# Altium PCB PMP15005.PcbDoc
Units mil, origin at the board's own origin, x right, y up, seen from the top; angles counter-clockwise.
Board outline 2000 x 1700 mil, 2 copper layers (Top Layer, Bottom Layer), stack 61.6 mil thick; 50 components, 16 nets, 81 pads, 20 vias.
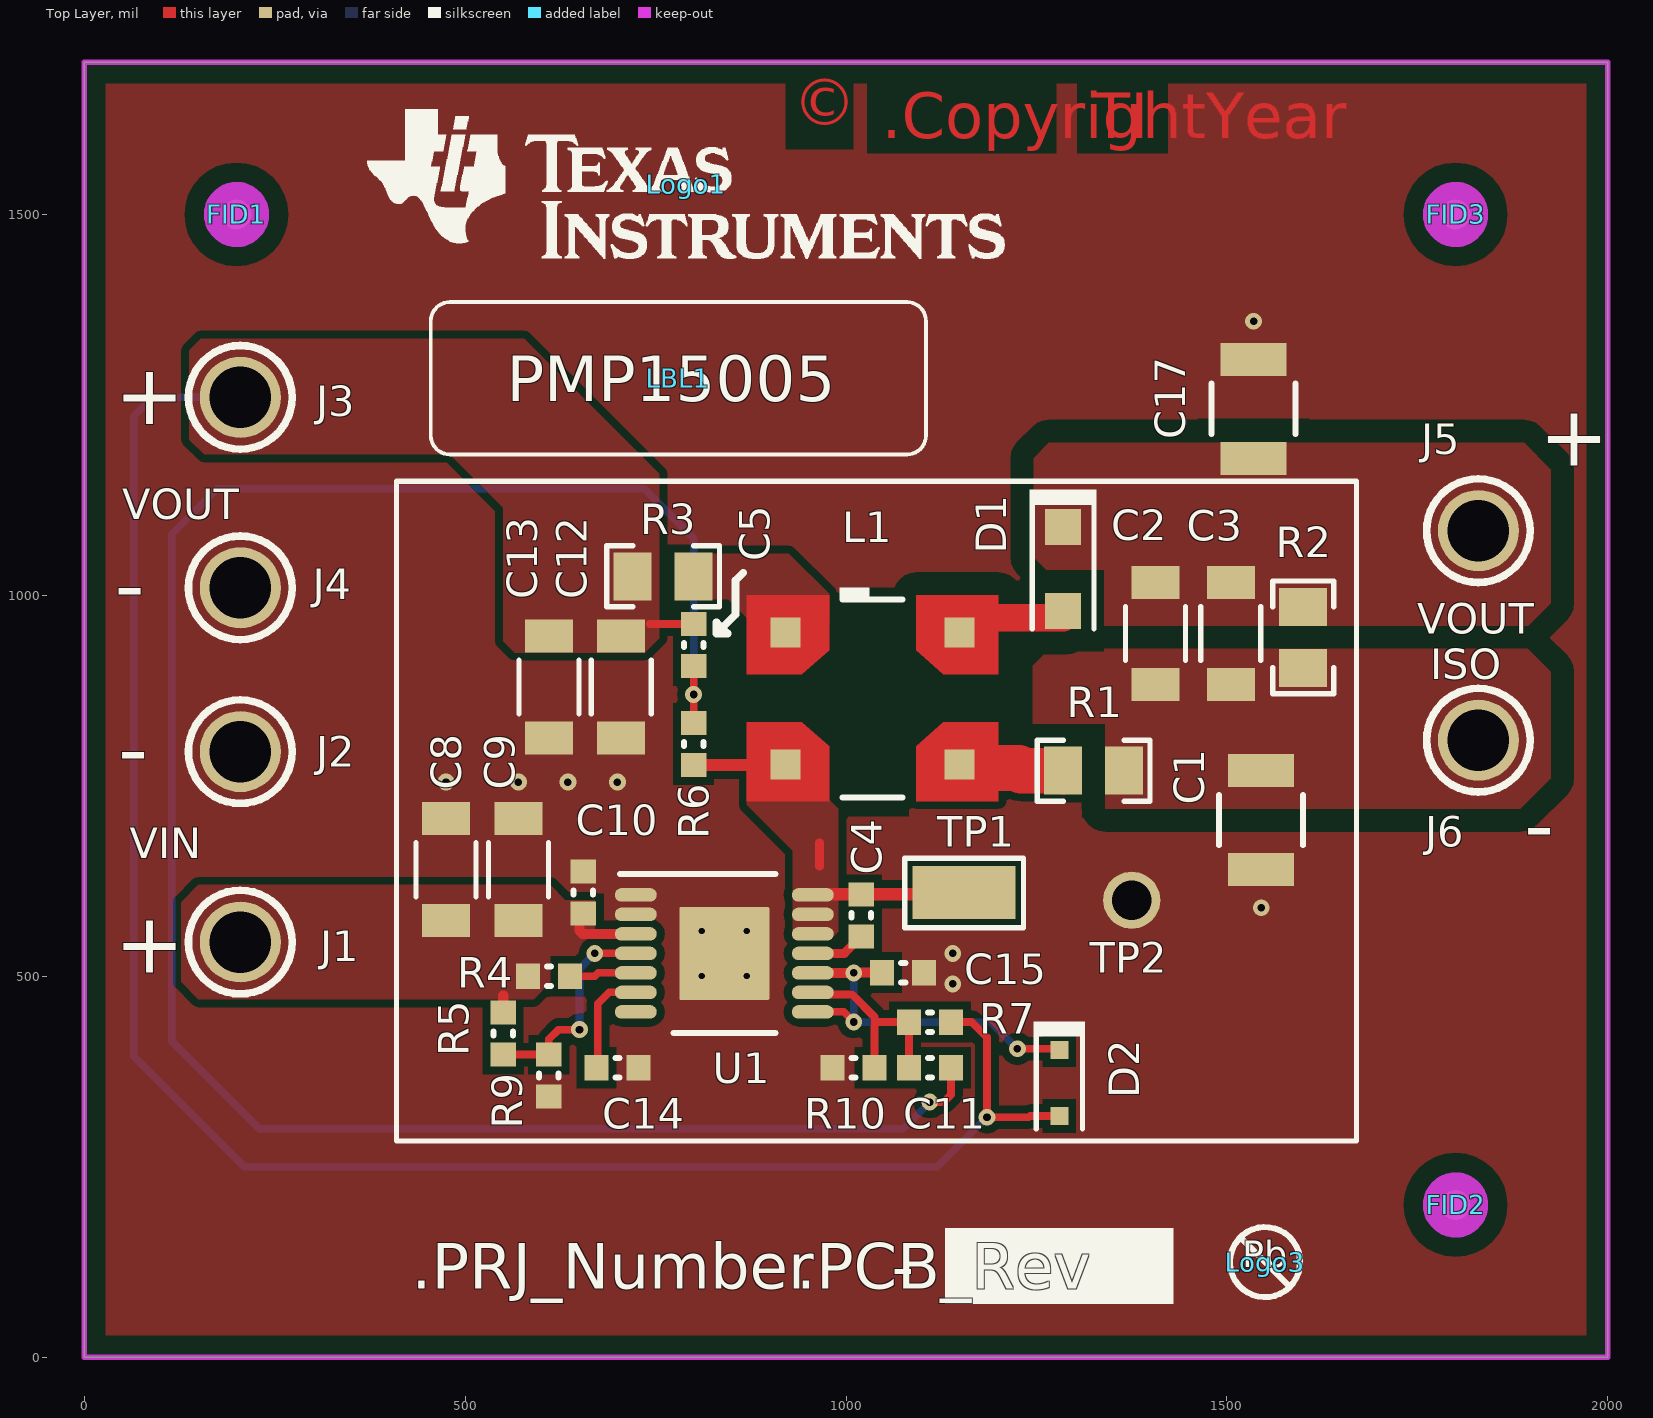
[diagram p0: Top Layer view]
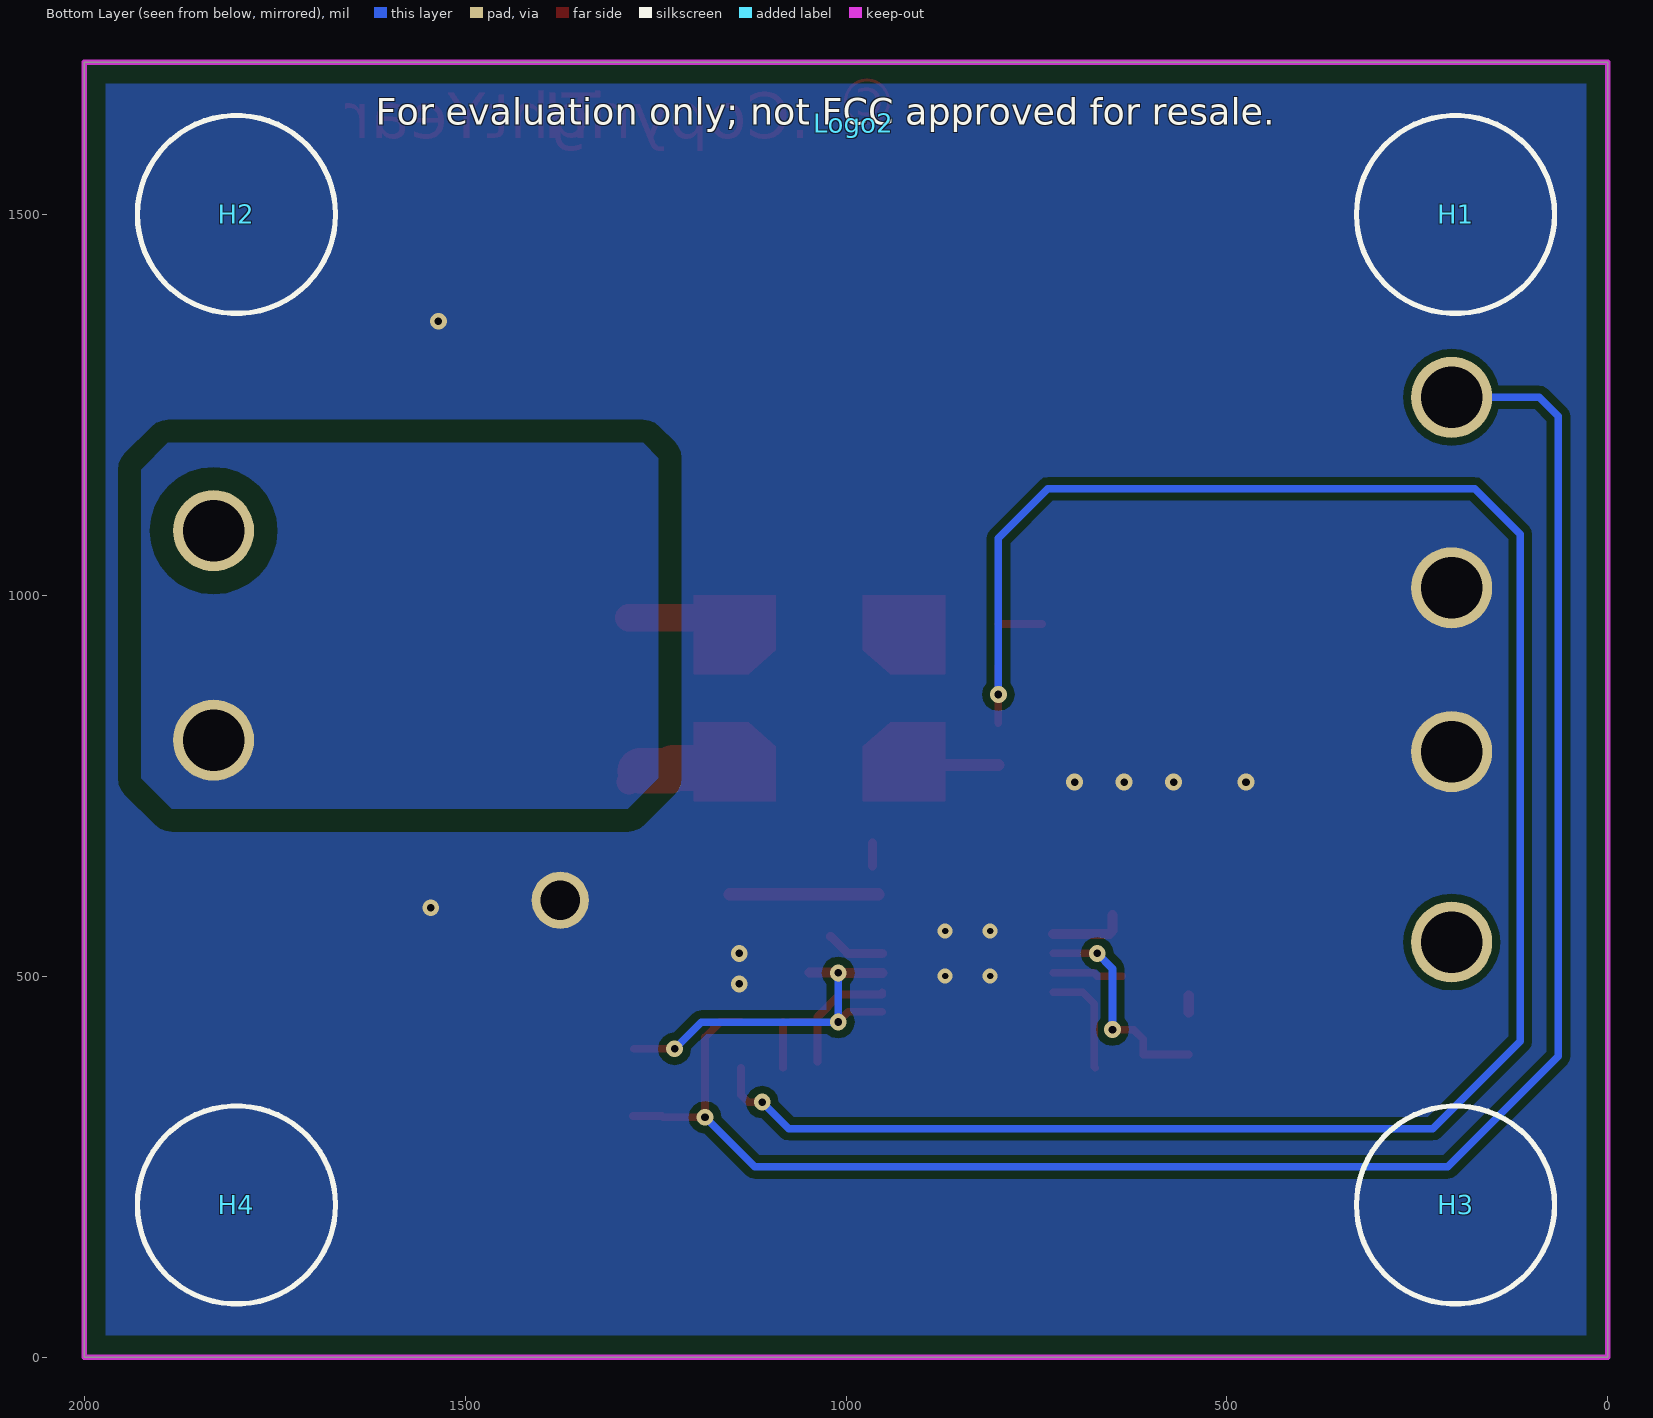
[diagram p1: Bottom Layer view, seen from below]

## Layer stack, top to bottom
Top Solder: solder mask 0.4, Solder Resist, Dk 3.5
Top Layer: signal copper 2.8
Dielectric1: core 56, FR-4, Dk 4.8
Bottom Layer: signal copper 2.8
Bottom Solder: solder mask 0.4, Solder Resist, Dk 3.5

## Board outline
0,0 2000,0 2000,1700 0,1700

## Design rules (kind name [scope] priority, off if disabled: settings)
AcuteAngle [All] p1: minimum=4.50000000000000E+0001 checktracksonly=FALSE
AssemblyTestPointUsage [All] p1: valid=2
Clearance Clearance_ISOPoly [(InNet('ISOGND') OR InNet('VOUTISO') OR InNet ('NetR1_1') OR InNet ('NetD1_2')) OR InNet ('NetL1_9') OR InNet ('NetL1_8')] p1: gap=30
Clearance Clearance_Keepouts [((IsTrack Or IsArc) And Not InPoly) And IsFree and IsKeepOut vs ((IsTrack Or IsArc) And Not InPoly) And IsFree and IsKeepOut] p2: gap=0
Clearance Clearance_BoardEdge_MountingHoles [OnCopper and InComponentClass('Mounting Holes') vs IsKeepOut] p3: gap=40
Clearance Clearance_BoardEdge_Poly [OnCopper and InPoly vs IsKeepOut] p4: gap=25
Clearance Clearance_BoardEdge [OnCopper and Not InComponentClass('Logo') and not InComponentClass('FiducialMark') and not InRegion(1000,500,4000,800) and Not IsKeepout vs IsKeepOut] p5: gap=50
Clearance Clearance_Poly [InPolygon] p6: gap=10
Clearance [All] p7: gap=7.87
ComponentClearance ComponentClearance_MountingHoles_FiducialMarks [InComponentClass('Mounting Holes') vs InComponentClass('FiducialMark')] p1: gap=50 collisioncheckmode=3 verticalgap=10 showdistances=FALSE
ComponentClearance ComponentClearance_Shunt [InComponentClass('Header') vs InComponentClass('Shunt')] p2: gap=0 collisioncheckmode=3 verticalgap=0 showdistances=FALSE
ComponentClearance ComponentClearance_Logo [InComponentClass('Logo')] p3: gap=20 collisioncheckmode=3 verticalgap=10 showdistances=FALSE
ComponentClearance ComponentClearance_ScrewToNut [(HasFootprint('NY PMS 440 0025 PH')) vs (HasFootprint('Keystone_1902C'))] p4: gap=5 collisioncheckmode=3 verticalgap=10 showdistances=FALSE
ComponentClearance ComponentClearance_MountingHoles [InComponentClass('Mounting Holes')] p5: gap=250 collisioncheckmode=3 verticalgap=100000 showdistances=FALSE
ComponentClearance ComponentClearance_SmallPassives [HasFootprint('0201*') or HasFootprint('0402*') or HasFootprint('0508') or HasFootprint('0603*') or HasFootprint('0612') or HasFootprint('0805*') or HasFootprint('0815*') or HasFootprint('0830*') or HasFootprint('1206*') or HasFootprint('1210*') or HasFootprint('1808*') or HasFootprint('1812*') or HasFootprint('1825*') or HasFootprint('2010*') or HasFootprint('2220*') or HasFootprint('2225*') or HasFootprint('2512*') or HasFootprint('2728*') or HasFootprint('3518*') vs HasFootprint('0201*') or HasFootprint('0402*') or HasFootprint('0508') or HasFootprint('0603*') or HasFootprint('0612') or HasFootprint('0805*') or HasFootprint('0815*') or HasFootprint('0830*') or HasFootprint('1206*') or HasFootprint('1210*') or HasFootprint('1808*') or HasFootprint('1812*') or HasFootprint('1825*') or HasFootprint('2010*') or HasFootprint('2220*') or HasFootprint('2225*') or HasFootprint('2512*') or HasFootprint('2728*') or HasFootprint('3518*')] p6: gap=20 collisioncheckmode=3 verticalgap=10 showdistances=FALSE
ComponentClearance ComponentClearance_THtoSMT [IsThruComponent vs IsSMTComponent] p7: gap=20 collisioncheckmode=3 verticalgap=30 showdistances=FALSE
ComponentClearance ComponentClearance_THtoTH [IsThruComponent vs IsThruComponent] p8: gap=50 collisioncheckmode=3 verticalgap=30 showdistances=FALSE
ComponentClearance [All] p9: gap=20 collisioncheckmode=3 verticalgap=10 showdistances=FALSE
DiffPairsRouting [All] p1: maxlimit=100 minlimit=10 mostfreqgap=10 toplayer_minwidth=15 toplayer_maxwidth=15 toplayer_prefwidth=15 bottomlayer_minwidth=15 bottomlayer_maxwidth=15 bottomlayer_prefwidth=15 maxuncoupledlength=1000
FabricationTestPointUsage TestPointUsage [All] p1: valid=2 allowmultiple=FALSE
FabricationTestpoint Testpoint [All] p1: side=3 testpointundercomponent=TRUE minsize=40 maxsize=100 preferedsize=60 minholesize=0 maxholesize=40 preferedholesize=32 testpointgrid=1 allowsidetop=TRUE allowsidebottom=TRUE usegrid=TRUE gridtolerance=0.01
FanoutControl Fanout_LCC [IsLCC] p1: bgadir=Out bgaviamode=Centered fanoutstyle=Auto fanoutdirection=Alternating viagrid=1 // Fanout_LCC (Default Rule)
FanoutControl Fanout_BGA [IsBGA] p2: bgadir=Out bgaviamode=Centered fanoutstyle=Auto fanoutdirection=Alternating viagrid=1 // Fanout_BGA (Default Rule)
FanoutControl Fanout_Default [All] p4: bgadir=Out bgaviamode=Centered fanoutstyle=Auto fanoutdirection=Alternating viagrid=1 // Fanout_Default (Default Rule)
FanoutControl Fanout_Small [(CompPinCount < 5)] p5: bgadir=Out bgaviamode=Centered fanoutstyle=Auto fanoutdirection=OutThenIn viagrid=1 // Fanout_Small (Default Rule)
HoleSize [All] p1: absolutevalues=TRUE maxlimit=251 minlimit=7.87 maxpercent=80.000 minpercent=20.000
MinimumAnnularRing MinimumAnnularRing_ThermalPadVias [IsVia and InAnyComponent] p1: minimumring=3.87
MinimumAnnularRing [All] p2: minimumring=6
MinimumSolderMaskSliver MinimumSolderMaskSliver_Logo [InComponentClass('Logo') vs InComponentClass('Logo')] p1: minsoldermaskwidth=0.7
MinimumSolderMaskSliver [All] p2: minsoldermaskwidth=3.94
PlaneConnect [All] p1: planeconnectstyle=Relief reliefexpansion=10 reliefentries=4 reliefconductorwidth=10 reliefairgap=10
PolygonConnect [All] p1: connectstyle=Direct reliefconductorwidth=10 reliefentries=4 polygonreliefangle="90 Angle" airgapwidth=10
RoutingVias ThermalPadVias [IsVia and InAnyComponent] p1: holewidth=7.87 width=19.68 viastyle="Through Hole" minholewidth=7.87 minwidth=15.75 maxholewidth=12.99 maxwidth=23.62
RoutingVias [All] p2: holewidth=10 width=22 viastyle="Through Hole" minholewidth=7.87 minwidth=12.99 maxholewidth=40 maxwidth=65
SilkToBoardRegionClearance [Not ((IsComment or IsDesignator) And (Hide <> 'False')) and not InRegion(1000,500,4000,800)] p1:
SilkToSilkClearance SilkToSilkClearance_Pb-FreeLogo [(HasFootprint('Pb-Free_Overlay_Medium') OR HasFootprint('Pb-Free_Overlay_Small')) vs (HasFootprint('Pb-Free_Overlay_Medium') OR HasFootprint('Pb-Free_Overlay_Small'))] p1: silktosilkclearance=0
SilkToSilkClearance [All] p2: silktosilkclearance=5
SilkToSolderMaskClearance "Silk to Solder Mask Opening" [All] p1: minsilkscreentomaskgap=1 clearancetoexposedcopper=FALSE
SolderMaskExpansion [All] p1: expansion=1.97
Width [All] p1: maxlimit=100 minlimit=6 preferedwidth=10 checkconnectedcopper=TRUE
15 further rules are at their usual default settings.

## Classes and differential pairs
component class Label: LBL1
component class AssemblyNote: ZZ1 ZZ2 ZZ3 ZZ4
component class FiducialMark: FID1 FID2 FID3
component class Logo: Logo1

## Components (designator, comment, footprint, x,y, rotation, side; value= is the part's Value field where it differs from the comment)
C1 "202S41W222KV4E" 1210_280 1545,705 r90 top
C2 "C3216X7R1E106M160AE" 1206_190 1406.24,950.12 r90 top
C3 "C3216X7R1E106M160AE" 1206_190 1505,950 r90 top
C4 "GRM188R71C103KA01D" 0603L 1020.24,580.12 r270 top
C5 "GRM188R72A102KA01D" 0603L 800,935 r270 top
C8 "GRM31CR72A225KA73L" 1206_190 475,640 r90 top
C9 "GRM31CR72A225KA73L" 1206_190 570,640 r90 top
C10 "GRM188R72A104KA35D" 0603L 655.24,610.12 r90 top
C11 "C0603X103K5RACTU" 0603L 1110.24,380.12 r180 top
C12 "C3216X7R1E106M160AE" 1206_190 705,880 r270 top
C13 "C3216X7R1E106M160AE" 1206_190 610,880 r270 top
C14 "0603YC823KAT2A" 0603L 700.24,380.12 r0 top
C15 "C1608X7R1C105K" 0603L 1075,505 r0 top
C17 "202S41W222KV4E" 1210_280 1535,1245 r270 top
D1 "PMEG6010CEH,115" SOD-123F 1285,1035 r270 top
D2 "SD103AWS-7-F" sod-323 1280,360 r270 top
FID1 "Fiducial" Fiducial10-20 200,1500 r0 top
FID2 "Fiducial" Fiducial10-20 1800,200 r0 top
FID3 "Fiducial" Fiducial10-20 1800,1500 r0 top
H1 "SJ5382" 3M_SJ5382 200,1500 r180 bottom locked
H2 "SJ5382" 3M_SJ5382 1800,1500 r180 bottom locked
H3 "SJ5382" 3M_SJ5382 200,200 r180 bottom locked
H4 "SJ5382" 3M_SJ5382 1800,200 r180 bottom locked
J1 "Suggest using a net name here" Keystone1573-2 205,545 r90 top
J2 "Suggest using a net name here" Keystone1573-2 205,795 r270 top
J3 "Suggest using a net name here" Keystone1573-2 205,1260 r270 top
J4 "Suggest using a net name here" Keystone1573-2 205,1010 r0 top
J5 "Suggest using a net name here" Keystone1573-2 1830,1085 r0 top
J6 "Suggest using a net name here" Keystone1573-2 1830,810 r0 top
L1 "33uH" LPR8035V-223x 1035,865 r0 top
LBL1 "PMP15005" Label_650x200 780,1285 r0 top
Logo1 "Texas Instruments" TI_Stacked_Overlay_Small 790,1540 r0 top
Logo2 "FCC disclaimer" FCC_disclaimer 990,1620 r180 bottom
Logo3 "Pb-Free Symbol" Pb-Free_Overlay_Small 1550,125 r0 top
R1 "CRCW08050000Z0EA" 0805_HV 1325,770 r0 top
R2 "CRCW08051K00FKEA" 0805_HV 1600,945 r270 top
R3 "CRCW08050000Z0EA" 0805_HV 760,1025 r0 top
R4 "CRCW0603169KFKEA" 0603L 610.24,500.12 r0 top
R5 "CRCW060349K9FKEA" 0603L 550,425 r90 top
R6 "CRCW0603100KFKEA" 0603L 800,805 r90 top
R7 "CRCW06033K48FKEA" 0603L 1110.24,440.12 r0 top
R9 "CRCW06035K23FKEA" 0603L 610,370 r90 top
R10 "CRCW06032K00FKEA" 0603L 1009.86,380.12 r0 top
TP1 "5015" Testpoint_Keystone_Miniature 1155,610 r0 top
TP2 "1040" CONN_1040 1375,600 r90 top
U1 "LM5160AQPWPRQ1" PWP0014A_N 840.24,530.12 r0 top
ZZ1 "Install label in silk screened box after final wash.  Text shall be 8 pt. font.  Text shall be per Label Table." AssemblyNoteLabel 270,3230 r0 top
ZZ2 "These assemblies are ESD sensitive, ESD precautions shall be observed." AssemblyNote 270,3100 r0 top
ZZ3 "These assemblies must be clean and free from flux and all contaminants. Use of no clean flux is not acceptable." AssemblyNote 270,3000 r0 top
ZZ4 "must comply with workmanship standards IPC-A-610 Class 2., unless otherwise specified." AssemblyNote 270,2900 r0 top

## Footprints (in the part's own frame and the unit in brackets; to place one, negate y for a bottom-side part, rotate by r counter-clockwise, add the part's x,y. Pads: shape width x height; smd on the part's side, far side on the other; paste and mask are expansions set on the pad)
3M_SJ5382 [mil] "3M BUMPON"
  silkscreen extent -130,-130 130,130, body extent -124,-125 125,125, height 73
0603L [mm] "0603 from SM-752 data"
  rect 0.8x0.85 smd: 1(-0.7,0) 2(0.7,0)
  silkscreen extent -0.07,-0.33 0.07,0.33, body extent -0.87,-0.47 0.87,0.47, height 1
0805_HV [mil] "0805 with 30mil clearance between pads"
  rect 50x63 smd: 1(-40,0) 2(40,0)
  silkscreen extent -74,-40 74,40, body extent -43,-29 43,29, height 57
1206_190 [mm] "1206_190"
  rect 1.1x1.6 smd: 1(-1.7,0) 2(1.7,0)
  silkscreen extent -0.9,-1 0.9,1, body extent -1.75,-0.95 1.75,0.95, height 1.9
1210_280 [mm] "SMD, 2-Leads, Body 3.6x2.8mm, Height 2.8mm"
  rect 1.1x2.2 smd: 1(-1.65,0) 2(1.65,0)
  silkscreen extent -0.84,-1.4 0.84,1.4, body extent -1.8,-1.4 1.8,1.4, height 2.8
AssemblyNote [mil] "Assembly Note"
AssemblyNoteLabel [mil] "Assembly Note for PCB Labels"
CONN_1040 [mil] "Test Point, PC  test point Terminal"
  round 75 hole 52: 1(0,0)
  body extent -55,-12 55,13, height 276
FCC_disclaimer [mil]
Fiducial10-20 [mm]
  round 1 smd mask+0.5: 1(0,0)
  Top Layer keep-out circle w1.178: c0,0 r0.5
Keystone1573-2 [mm] "Double Turret"
  round 2.7 hole 2.05: 1(0,0)
  silkscreen extent -1.73,-1.73 1.73,1.73, body extent -1.18,-1.18 1.17,1.18, height 4.72
Label_650x200 [mil] "Thermal Transfer Label"
  round 1 on Mech13: 0(0,0)
  silkscreen extent -325,-100 325,100, body extent -325,-100 325,100, height 1
LPR8035V-223x [mm] "SMD, 4-Leads, Body 7.92x6.4mm"
  rect 1x1 smd: 1(-2.9,2.2) 2(-2.9,-2.2) 3(2.9,-2.2) 4(2.9,2.2)
  Top Layer region: 1.455,-3.43 1.455,-1.6 2.36,-0.8 4.19,-0.8 4.19,-3.43
  Top Layer region: -4.19,-3.43 -4.19,-0.8 -2.36,-0.8 -1.455,-1.6 -1.455,-3.43
  Top Layer region: 1.455,1.6 2.36,0.8 4.19,0.8 4.19,3.43 1.455,3.43
  Top Layer region: -4.19,0.8 -4.19,3.43 -1.455,3.43 -1.455,1.6 -2.36,0.8
  silkscreen extent -1.1,-3.3 1,3.7, body extent -4,-3.24 4,3.24, height 3.51
Pb-Free_Overlay_Small [mil]
  silkscreen extent -46,-46 46,46
PWP0014A_N [mm] "TSOP, 14-Leads, Body 5x4.4mm, Pitch 0.65mm, Thermal Pad 3x3.1 mm, IPC Medium Density"
  rrect100% 1.4x0.45 smd: 1(-2.95,1.95) 2(-2.95,1.3) 3(-2.95,0.65) 4(-2.95,0) 5(-2.95,-0.65) 6(-2.95,-1.3) 7(-2.95,-1.95) 8(2.95,-1.95) 9(2.95,-1.3) 10(2.95,-0.65) 11(2.95,0) 12(2.95,0.65) 13(2.95,1.3) 14(2.95,1.95)
  rrect3% 3x3.1 smd: 15(0,0)
  silkscreen extent -3.47,-2.65 1.7,2.65, body extent -3.21,-2.5 3.21,2.5, height 1
SOD-123F [mm] "NXP recommended land pattern"
  rect 1.2x1.2 smd paste-0.05: 1(-1.4,0) 2(1.4,0)
  silkscreen extent -2.64,-1.12 2.01,1.12, body extent -1.8,-0.85 1.8,0.85, height 1.2
sod-323 [mm] "NXP recommended land pattern"
  rect 0.6x0.6 smd paste-0.05: 1(-1.1,0) 2(1.1,0)
  silkscreen extent -2.06,-0.86 1.53,0.86, body extent -1.3,-0.67 1.3,0.68, height 1.1
Testpoint_Keystone_Miniature [mil] "Miniature SMT test point"
  rect 135x70 smd: 1(0,0)
  silkscreen extent -78,-46 78,45, body extent -52,-20 52,20, height 61
TI_Stacked_Overlay_Small [mil]
  silkscreen extent -418,-98 418,98

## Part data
C1 C17: "CAP, CERM, 2200 pF, 2000 V, +/- 10%, X7R, 1210"
C2 C3 C12 C13: "CAP, CERM, 10 µF, 25 V, +/- 20%, X7R, 1206_190"
C4: "CAP, CERM, 0.01uF, 16V, +/-10%, X7R, 0603"
C5: "CAP, CERM, 1000 pF, 100 V, +/- 10%, X7R, 0603"
C8 C9: "CAP, CERM, 2.2 µF, 100 V, +/- 10%, X7R, 1206_190"
C10: "CAP, CERM, 0.1 µF, 100 V, +/- 10%, X7R, 0603"
C11: "CAP, CERM, 0.01 µF, 50 V, +/- 10%, X7R, 0603"
C14: "CAP, CERM, 0.082 µF, 16 V, +/- 10%, X7R, 0603"
C15: "CAP, CERM, 1uF, 16V, +/-10%, X7R, 0603"
D1: "Diode, Schottky, 60 V, 1 A, SOD-123F"
D2: "Diode, Schottky, 40 V, 0.35 A, SOD-323"
FID1 FID2 FID3: "Fiducial mark.  There is nothing to buy or mount."
H1 H2 H3 H4: "Bumpon, Hemisphere, 0.25 X 0.075, Clear"
J1 J2 J3 J4 J5 J6: library part 1573-2, "Terminal, Turret, TH, Double"
L1: library part LPR8035V-333MR, "Coupled inductor, 33 µH, 0.75 A, 0.2 ohm, SMD"
LBL1: library part THT-13-457-10, "Thermal Transfer Printable Labels, 1.250\" W x 0.250\" H - 10,000 per roll"
Logo1: library part TI_Logo, "Texas Instrument Corporate Signature"
Logo2: library part FCC_disclaimer, "FCC_disclaimer"
Logo3: library part Pb-Free
R1 R3: "RES, 0 ohm, 5%, 0.125W, 0805"
R2: "RES, 1.00 k, 1%, 0.125 W, 0805"
R4: "RES, 169 k, 1%, 0.1 W, 0603"
R5: "RES, 49.9 k, 1%, 0.1 W, 0603"
R6: "RES, 100 k, 1%, 0.1 W, 0603"
R7: "RES, 3.48 k, 1%, 0.1 W, 0603"
R9: "RES, 5.23 k, 1%, 0.1 W, 0603"
R10: "RES, 2.00k ohm, 1%, 0.1W, 0603"
TP1: "Test Point, Miniature, SMT"
TP2: "TEST POINT SLOTTED .118\", TH"
U1: "Wide Input 65V, 1.5A Synchronous Step-Down DC-DC Converter, PWP0014A"
ZZ1: library part AssemblyNoteLabel
ZZ2 ZZ3 ZZ4: library part AssemblyNote

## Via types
v1: diameter 22, hole 10, Top Layer to Bottom Layer, tented both sides, 16 vias
v2: diameter 19.68, hole 8, Top Layer to Bottom Layer, 4 vias

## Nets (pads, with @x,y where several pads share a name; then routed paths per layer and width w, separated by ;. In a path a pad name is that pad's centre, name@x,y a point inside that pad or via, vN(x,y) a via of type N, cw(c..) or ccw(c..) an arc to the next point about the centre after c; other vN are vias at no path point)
GND: C1.1 C8.2 C9.2 C10.2 C12.2 C13.2 C14.2 C15.2 C17.1 J2.1 J4.1 R9.1 R10.1 TP2.1 U1.1 U1.2 U1.15
  other v1: 1140.24,490.12 1140.24,530.12 1545,590 475,755 570,755 635,755 700,755 1535,1360
  other v2: 810.71,500.59 869.76,500.59 810.71,559.65 869.76,559.65
ISOGND: C1.2 C2.1 C3.1 J6.1 R1.2 R2.2
NetC4_2: C4.2 U1.11 | length 77.1
  Top Layer w12: U1.11@952.44,530.12 997.8,530.12 C4.2
NetC5_2: C5.2 C11.1 R6.2 | length 2806
  Top Layer w10: R6.2 v1(800,870) C5.2 ; v1(1110,335) 1128.04,335 1137.8,344.75 C11.1
  Bottom Layer w10: v1(800,870) 800,1075 735,1140 175,1140 115,1080 115,415 230,300 1075,300 v1(1110,335)
NetC11_2: C11.2 R7.1 R10.2 U1.9 | length 254
  Top Layer w10: U1.9@952.44,478.94 952.44,476.24 1007.87,476.24 1037.42,446.7 1037.42,440.12 ; R10.2@1037.42,387.86 1037.42,440.12 ; R7.1@1072.68,440.12 1037.42,440.12 ; C11.2 R7.1
NetC14_1: C14.1 U1.6 | length 144.6
  Top Layer w10: C14.1 674.11,381.55 674.11,463.99 689.06,478.94 U1.6@728.03,478.94
NetC15_1: C15.1 D2.1 U1.8 U1.10 | length 503.1
  Top Layer w10: U1.8@952.44,453.35 997.01,453.35 v1(1010.24,440.12) ; v1(1225,405) D2.1@1278.31,405
  Top Layer w13.5: U1.10@952.44,504.53 U1.10 v1@1005.83,504.53 ; v1@1010.24,500.12 1015.12,505 C15.1
  Bottom Layer w10: v1(1010.24,440.12) v1@1010.24,440 ; v1(1010.24,504.53) v1@1010.24,440 ; v1(1225,405) 1190,440 v1@1010.24,440
NetD1_2: D1.2 L1.4 | length 140.7
  Top Layer w32: L1.4@1154.17,946.61 1178.09,970.53
  Top Layer w36: 1178.09,970.53 D1.2@1285,970.53
NetL1_1: L1.1 R3.2
NetL1_3: L1.3 R1.1 | length 138.4
  Top Layer w32: R1.1@1270,770 R1.1@1285,755
  Top Layer w60: L1.3@1154.17,773.39 1226.61,773.39 1230,770 R1.1@1270,770
NetR4_2: R4.2 U1.5 | length 92.1
  Top Layer w10: R4.2 670.24,500.12 674.65,504.53 U1.5@728.03,504.53
NetR5_1: R5.1 R9.2 U1.4 | length 291.5
  Top Layer w10: R5.1 609.88,397.44 R9.2 610,417.44 622.68,430.12 v1(650.24,430.12) ; v1(670.24,530.12) U1.4@728.03,530.12
  Bottom Layer w10: v1(650.24,430.12) 650.24,510.12 v1(670.24,530.12)
SW: C4.1 L1.2 R6.1 TP1.1 U1.12 U1.13 U1.14 | length 345.4
  Top Layer w12: 965,645 965,675
  Top Layer w16: R6.1 L1.2@919.88,777.44 ; U1.14@957.17,607.68 C4.1 TP1.1@1152.68,607.68
VIN: C8.1 C9.1 C10.1 J1.1 R4.1 R5.2 U1.3 | length 122.1
  Top Layer w13.5: R5.2 550,475 ; C10.1@650.24,580.12 650.24,560.12 654.65,555.71 659.59,555.71 ; 659.62,555.74 680.85,555.74 ; 680.88,555.71 U1.3@728.03,555.71
VOUT: C5.1 C12.1 C13.1 D2.2 J3.1 R3.1 R7.2 | length 2511.1
  Top Layer w10: 742.44,962.56 C5.1 ; R7.2 1164.88,440.12 1185,420 v1(1185,315) 1240,315 1241.69,316.69 D2.2
  Bottom Layer w10: J3.1 90,1260 65,1235 65,395 210,250 1120,250 v1(1185,315)
VOUTISO: C2.2 C3.2 C17.2 D1.1 J5.1 R2.1
pads on no net: FID1.1 FID2.1 FID3.1 LBL1.0 U1.7

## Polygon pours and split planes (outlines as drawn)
GND on Top Layer "Top Layer-No Net1" (solid, pour order 16): 8.49,-6.35 1995,-6.35 1995,1695 8.49,1695
VOUT on Top Layer "Top Layer-No Net 3" (solid, pour order 13): 755,943.82 755,1160 578,1337 153.1,1337 138,1321.9 138,1204.5 157.5,1185 480,1185 550,1115 550,940.1 565.1,925 736.18,925
VIN on Top Layer "Top Layer-No Net" (solid, pour order 12): 150,620 360,620 608.39,620 611.61,620 631.61,600 670,600 670,550 590,470 315,470 150,470 127.33,492.67 127.33,597.33
ISOGND on Top Layer "Top Layer-No Net 4" (solid, remove dead copper, pour order 14): 1267.2,930 1895,930 1925,900 1925,760 1885.12,720.12 1278.15,720.12 1245.24,753.03 1245.24,908.03
VOUTISO on Top Layer "Top Layer-No Net 2" (solid, remove dead copper, pour order 15): 1895.64,960.12 1336.24,960.12 1246.24,1050.12 1246.24,1180.12 1266.24,1200.12 1889.88,1200.12 1925,1165 1925,989.48
SW on Top Layer "Top Layer-No Net 1" (solid, remove dead copper, pour order 10): 930.24,551.39 930.24,664.76 870.04,724.96 870.04,775 935,775 990,720 990,551.39
NetL1_1 on Top Layer "Top Layer-No Net 5" (solid, pour order 11): 875.33,965 845.34,995 790.59,995 790.59,1055 925,1055 977.72,1002.28 977.72,965
GND on Bottom Layer "Top Layer-No Net2" (solid, pour order 18): 4.88,0.97 2000,0.97 2000,1695 4.88,1695
ISOGND on Bottom Layer "Top Layer-No Net 6" (solid, remove dead copper, pour order 17): 1925,760 1925,1165 1889.88,1200.12 1266.24,1200.12 1246.24,1180.12 1246.24,760.12 1286.24,720.12 1885.12,720.12

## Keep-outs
Keep-Out Layer:
  the board outline again, w7
  text ".Layer_Name" at 577,-858.49 h60

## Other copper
Top Layer:
  pour cut-out: 1082.09,710 992.76,710 992.76,801.48 934.62,859.62 992.62,917.62 992.62,1010 1082.09,1010 1082.09,920.53 1133.96,868.66 1082.09,816.78
  pour cut-out: 960,840 818.7,840 818.7,970 864.94,970 864.94,887.19 867.98,884.14 868.84,885 960,885
  pour cut-out: 1110,890 1215,890 1215,841.14 1106.45,841.14
  text ".CopyrightYear" at 1047,1600 h60
  text "TI" at 1323,1600 h60
  text "©" at 930,1596.48 h105
  text ".Layer_Name" at 577,-858.49 h60
Bottom Layer:
  text ".Layer_Name" at 577,-858.49 h60

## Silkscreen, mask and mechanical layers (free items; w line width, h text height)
Top Overlay:
  region: 1430,170 1130,170 1130,70 1430,70
  lines w7: 410,284 410,1150 1670,1150 1670,284 410,284
  lines w10: 865,1030 855,1020 855,975 830,950 ; 830,950 845,950 830,965 830,950
  text "+" at 40,1225 h80
  text "+" at 1910,1170 h80
  text "VOUT" at 50,1100 h40
  text "-" at 40,975 h80
  text "VOUT /  ISO" at 1750,890 h40
  text "-" at 45,760 h80
  text "-" at 1890,660 h80
  text "VIN" at 60,655 h40
  text "+" at 40,505 h80
  text ".PRJ_Number" at 430,90 h60
  text ".PCB_Rev" at 935,90 h60
  text "-" at 1060,90.01 h60
  text ".Layer_Name" at 577,-858.49 h60
Bottom Overlay:
  text ".Layer_Name" at 577,-858.49 h60
Top Paste:
  text ".Layer_Name" at 577,-858.49 h60
Bottom Paste:
  text ".Layer_Name" at 577,-858.49 h60
Top Solder:
  text ".Layer_Name" at 577,-858.49 h60
  text ".Layer_Name" at 577,-858.49 h60
Bottom Solder:
  text ".Layer_Name" at 577,-858.49 h60
Drill Guide:
  text ".Layer_Name" at 577,-858.49 h60
M1 Board Outline:
  the board outline again, w10
  text ".Layer_Name" at 577,-858.49 h60
M2 Board Dimensions:
  rectangle: 125,-400 500,-275
  rectangle: 0,-275 125,-150
  lines w7: 0,-275 1000,-275 ; 125,-400 125,-150 ; 250,-400 250,-150 ; 500,-400 500,-150 ; 750,-400 750,-150 ; 0,-400 0,-150 1000,-150 1000,-400 0,-400
  text ".Layer_Name" at 577,-858.49 h60
M3 3D STEP Top:
  text ".Layer_Name" at 577,-858.49 h60
M4 3D STEP Bottom:
  text ".Layer_Name" at 577,-858.49 h60
M5 Assembly Top:
  lines w10: -292,-930.17 6308,-930.17 ; -292,-726.83 6310,-726.83 ; -292,-523.5 -292,-1133.5 3713,-1133.5 6310,-1133.5 6310,-523.5 -291.5,-523.5 -291.5,-1133.5 1284,-1133.5 ; 2173,-1133.5 2173,-523.5 ; 3440,-726.83 3440,-523.5 ; 4280,-726.83 4280,-523.5 ; 4902,-1140 4902,-937.17
  text "COMPONENTS MARKED 'DNP' SHOULD NOT BE POPULATED." at 1153.5,-318.5 h60
  text "ASSEMBLY VARIANT:" at 1153,-434 h60
  text ".VariantName" at 2189,-434 h60
  text "PCB VIEWED FROM TOP SIDE" at -228.5,-655.67 h60
  text "BOARD #:" at 2248,-655.67 h60
  text ".PRJ_Number" at 2793.5,-655.67 h60
  text "REV:" at 3638,-655.67 h60
  text ".PCB_Rev" at 3929.5,-655.67 h60
  text "SVN REV:" at 4476,-655.67 h60
  text ".VersionControl_RevNumber" at 4982,-655.67 h60
  text "TID #:" at 2248,-859 h60
  text ".TID" at 2793.5,-859 h60
  text "PLOT NAME =" at -228.5,-1064.34 h60
  text ".plot_File_Name" at 577,-1064.34 h60
  text "GENERATED    :" at 2250,-1064.34 h60
  text ".Print_Date" at 3119.5,-1064.34 h60
  text ".Print_Time" at 3848.5,-1064.34 h60
  text "TEXAS INSTRUMENTS" at 5113,-1064.34 h60
M6 Assembly Bottom:
  lines w10: -292.5,-727.33 6309.5,-727.33 ; -290.5,-930.67 6309.5,-930.67 ; 1115.5,-1140.5 1115.5,-937.67 ; 1737.5,-727.33 1737.5,-524 ; 2577.5,-727.33 2577.5,-524 ; 3844.5,-1134 3844.5,-524 ; 4733.5,-1134 6309,-1134 6309,-524 -292.5,-524 -292.5,-1134 2304.5,-1134 6309.5,-1134 6309.5,-524
  text "COMPONENTS MARKED 'DNP' SHOULD NOT BE POPULATED." at 6102,-318 h60
  text ".VariantName" at 5058,-434 h60
  text "ASSEMBLY VARIANT:" at 6097,-434 h60
  text ".VersionControl_RevNumber" at 1035.5,-656.17 h60
  text "SVN REV:" at 1541.5,-656.17 h60
  text ".PCB_Rev" at 2088,-656.17 h60
  text "REV:" at 2379.5,-656.17 h60
  text ".PRJ_Number" at 3224,-656.17 h60
  text "BOARD #:" at 3769.5,-656.17 h60
  text "PCB VIEWED FROM BOTTOM SIDE" at 6246,-656.17 h60
  text ".TID" at 3224,-859.5 h60
  text "TID #:" at 3769.5,-859.5 h60
  text "TEXAS INSTRUMENTS" at 904.5,-1064.84 h60
  text ".Print_Time" at 2169,-1064.84 h60
  text ".Print_Date" at 2898,-1064.84 h60
  text "GENERATED    :" at 3767.5,-1064.84 h60
  text ".plot_File_Name" at 5440.5,-1064.84 h60
  text "PLOT NAME =" at 6246,-1064.84 h60
M9 Title Sheet:
  drawing of 57 lines, arcs and shapes, not listed
  text "1" at 739.84,8036.5 h70
  text "2" at 3235.5,8036.5 h70
  text "3" at 5724.84,8036.5 h70
  text "4" at 8231.51,8036.5 h70
  text "5" at 10730.5,8036.5 h70
  text "6" at 13235.5,8036.5 h70
  text "A" at -416.5,6893.5 h70
  text "A" at 14383.5,6893.5 h70
  text "B" at -416.5,4513.5 h70
  text "B" at 14383.5,4513.5 h70
  text "C" at -416.5,2138.5 h70
  text "C" at 14383.5,2138.5 h70
  text "PROJECT TITLE:" at 11343.5,277.5 h45
  text ".PRJ_Title" at 11393.5,144.17 h70
  text "DESIGNED FOR:" at 11343.5,-23.5 h45
  text ".PRJ_Customer" at 11393.5,-163.5 h70
  text "D" at -416.5,-231.5 h70
  text "D" at 14383.5,-231.5 h70
  text "FILE NAME:" at 11343.5,-323.5 h45
  text ".PCB_File_Name_No_Path" at 11393.5,-443.5 h70
  text "Texas Instruments (TI) and/or its licensors do not warrant the accuracy or completeness of this specification" at 6374,-605.34 h45
  text "ENGINEER:" at 11343.5,-613.5 h45
  text "LAYOUT BY:" at 12848.5,-613.5 h45
  text "or any information contained therein. TI and/or its licensors do not warrant that this design will meet" at 6329.01,-718 h45
  text ".PRJ_Engineer" at 11393.5,-768.49 h70
  text ".PCB_Layout" at 12899,-768.49 h70
  text "the specifications, will be suitable for your application or fit for any particular purpose, or will operate in" at 6329.01,-830.67 h45
  text ".Layer_Name" at 577,-858.49 h60
  text "ALTIUM DESIGNER VERSION:" at 12848.5,-923.5 h45
  text "an implementation. TI and/or its licensors do not warrant that the design is production worthy. You should" at 6329.01,-943.33 h45
  text "completely validate and test your design implementation to confirm the system functionality for your application." at 6374,-1056 h45
  text ".print_Scale" at 11393.5,-1056.83 h70
  text ".Application_BuildNumber" at 12899,-1056.83 h70
  text "1" at 739.84,-1263.5 h70
  text "2" at 3235.5,-1263.5 h70
  text "3" at 5724.84,-1263.5 h70
  text "4" at 8231.51,-1263.5 h70
  text "5" at 10730.5,-1263.5 h70
  text "6" at 13235.5,-1263.5 h70
M10 Fab Notes:
  drawing of 185 lines, arcs and shapes, not listed
  text "DESIGN INFORMATION" at 12381.02,5910 h60
  text "MIN. TRACK WIDTH:" at 11736.46,5730 h60
  text "8" at 12832.7,5730 h60
  text "MIL" at 12987.46,5730 h60
  text "MIN. CLEARANCE:" at 11736.46,5598 h60
  text "0.2" at 12772.7,5598 h60
  text "mm" at 12987.46,5598 h60
  text "MIN. VIA PAD SIZE:" at 11736.46,5466 h60
  text "24" at 12802.71,5466 h60
  text "MIL" at 12987.46,5466 h60
  text "0.05mm (2MIL)" at 12431.46,5324.29 h60
  text "MINIMUM ANNULAR RING" at 11407.23,5320 h60
  text "EXTERNAL" at 13139.46,5320 h60
  text "PER" at 11607.23,5202 h60
  text "IPC-D-275 CLASS 2 LEVEL C" at 11827.23,5202 h60
  text "MIL, HOLES" at 13315.46,5089.71 h60
  text "+/-" at 12923,5089 h60
  text "+/-" at 13777,5089 h60
  text "REGISTRATION TOLERANCES:" at 11407.23,5084 h60
  text "METAL" at 12607,5084 h60
  text "5" at 13183.2,5084 h60
  text "3" at 14016.2,5084 h60
  text "MIL" at 14132.46,5084 h60
  text "MATERIAL:" at 11332.46,4874.54 h60
  text "FR-4 High Tg" at 12318.9,4734.21 h60
  text "FR-408" at 11753.46,4725.64 h60
  text "X" at 12165.46,4725.64 h60
  text "OTHER" at 13241.46,4725.64 h60
  text "62 MIL (1.6mm) +/-10%" at 12073.56,4562.92 h60
  text "THICKNESS:" at 11407.23,4558.64 h60
  text "X" at 11945.4,4558.64 h60
  text "OTHER" at 13358.46,4558.64 h60
  text "TOLERANCE:" at 11407.23,4400.64 h60
  text "X" at 12246.53,4400.64 h60
  text "ANSI IPC-6012 TYPE 3 CLASS 2" at 12433.48,4400.64 h60
  text "OTHER +/-" at 12433.46,4244.64 h60
  text "BOW & TWIST:" at 11407.23,4087.64 h60
  text "X" at 12246.53,4087.64 h60
  text "ANSI IPC-6012 TYPE 3 CLASS 2" at 12433.48,4087.64 h60
  text "OTHER +/-" at 12433.46,3929.13 h60
  text "DRILLING:" at 11332.46,3790.64 h60
  text "REFERENCE:" at 11407.23,3673.64 h60
  text "X" at 12055.46,3673.64 h60
  text "AS SHOWN" at 12242.46,3673.64 h60
  text "X" at 12956.46,3673.64 h60
  text "NC_DRILL FILES" at 13093.46,3673.64 h60
  text "PTH MIN COPPER THICKNESS:" at 11407.23,3515.64 h60
  text "X" at 12757.46,3515.64 h60
  text "1MIL" at 12894.46,3515.64 h60
  text "OTHER" at 13391.46,3515.64 h60
  text "BOARD FINISH:" at 11332.46,3356.64 h60
  text "SILKSCREEN:" at 11487.68,3238.64 h60
  text "X" at 12436.46,3238.64 h60
  text "TOP" at 12562.46,3238.64 h60
  text "X" at 12946.46,3238.64 h60
  text "BOTTOM" at 13073.46,3238.64 h60
  text "SILKSCREEN COLOR:" at 11487.68,3071.64 h60
  text "X" at 12435.42,3071.64 h60
  text "WHITE" at 12562.46,3071.64 h60
  text "OTHER" at 13073.46,3071.64 h60
  text "SOLDER RESIST COLOR:" at 11487.68,2901.64 h60
  text "X" at 12055.42,2742.44 h60
  text "GREEN" at 12182.46,2742.44 h60
  text "BLUE" at 12773.46,2742.44 h60
  text "OTHER" at 13311.46,2742.44 h60
  text "IMMERSION GOLD (ENIG)" at 12393.46,2553.92 h60
  text "ENEPIG" at 13731,2550.64 h60
  text "SURFACE FINISH:" at 11332.46,2549.64 h60
  text "X" at 12206.51,2549.64 h60
  text "IMM. TIN/SILVER OR EQUIV" at 11662,2392.64 h60
  text "OTHER" at 13093.46,2392.64 h60
  text "ARRAY/PANEL:" at 11332.46,2213.64 h60
  text "CUT AND TRIM PER MECH LAYER 1" at 12393.46,2209.35 h60
  text "N.C. ROUTE" at 12393.46,2057.64 h60
  text "X" at 13072.46,2057.64 h60
  text "V. SCORE" at 13259.46,2057.64 h60
  text "CERTIFICATION:" at 11332.46,1920.64 h60
  text "MATERIALS AND WORKMANSHIP FOR ALL PCBS" at 12057.46,1920.64 h60
  text "TO MEET OR EXCEED THE REQUIREMENTS OF:" at 12057.46,1822.64 h60
  text "X" at 11683.96,1686.13 h60
  text "ANSI IPC-A-600F CLASS ->" at 11822.96,1686.13 h60
  text "X" at 13462.02,1686.13 h60
  text "2" at 13580.96,1686.14 h60
  text "1" at 13265.96,1684.64 h60
  text "3" at 13934.96,1684.64 h60
  text "X" at 11686.02,1526.64 h60
  text "UL 94V-0" at 11822.96,1526.64 h60
  text "X" at 12498.02,1526.64 h60
  text "RoHS" at 12634.96,1526.64 h60
  text "OTHER" at 13279.36,1526.64 h60
  text "PER ORDER" at 13676.42,1526.64 h60
  text "ADDITIONAL REQUIREMENTS:" at 11332.46,1385.64 h60
  text "MICROSECTION:" at 11407.23,1270.64 h60
  text "YES" at 12312.96,1270.64 h60
  text "REQUIRED" at 13174.46,1114.49 h60
  text "BARE BOARD ELEC. TEST:" at 11407.23,1111.64 h60
  text "NONE" at 12712.96,1111.64 h60
  text "X" at 13047.46,1111.64 h60
  text "PER ORDER" at 13766.46,1111.64 h60
  text "MANUFACTURER'S UL:" at 11407.23,954.64 h60
  text "RAIL" at 12572.96,950.35 h60
  text "METAL" at 13064.77,950.35 h60
  text "X" at 13440,950 h60
  text "SILK" at 13576.46,950.35 h60
  text ".Layer_Name" at 577,-858.49 h60
M11 Gerber Information:
  lines w10: -292,-930.17 6308,-930.17 ; -292,-726.83 6310,-726.83 ; -292,-523.5 -292,-1133.5 3713,-1133.5 6310,-1133.5 6310,-523.5 -291.5,-523.5 -291.5,-1133.5 1284,-1133.5 ; 2173,-1133.5 2173,-523.5 ; 3440,-726.83 3440,-523.5 ; 4280,-726.83 4280,-523.5 ; 4902,-1140 4902,-937.17
  text "ALL ARTWORK VIEWED FROM TOP SIDE" at -228.5,-655.67 h60
  text "BOARD #:" at 2248,-655.67 h60
  text ".PRJ_Number" at 2793.5,-655.67 h60
  text "REV:" at 3638,-655.67 h60
  text ".PCB_Rev" at 3929.5,-655.67 h60
  text "SVN REV:" at 4476,-655.67 h60
  text ".VersionControl_RevNumber" at 4982,-655.67 h60
  text "LAYER NAME =" at -228.5,-858.49 h60
  text "TID #:" at 2248,-859 h60
  text ".TID" at 2793.5,-859 h60
  text "PLOT NAME =" at -228.5,-1064.34 h60
  text ".plot_File_Name" at 577,-1064.34 h60
  text "GENERATED    :" at 2250,-1064.34 h60
  text ".Print_Date" at 3119.5,-1064.34 h60
  text ".Print_Time" at 3848.5,-1064.34 h60
  text "TEXAS INSTRUMENTS" at 5113,-1064.34 h60
M12 Stackup:
  drawing of 191 lines, arcs and shapes, not listed
  text "Layer" at 9790.34,7830 h60
  text "Name" at 10200.26,7830 h60
  text "Material" at 11130,7830 h60
  text "Thickness" at 11989.77,7830 h60
  text "Constant" at 12639.6,7830 h60
  text "Board Layer Stack" at 13209.46,7830 h60
  text "1" at 9790.34,7710 h60
  text "Top Overlay" at 10200.26,7710 h60
  text "2" at 9790.34,7590 h60
  text "Top Solder" at 10200.26,7590 h60
  text "Solder Resist" at 11130,7590 h60
  text "0.40mil" at 11989.77,7590 h60
  text "3.5" at 12639.6,7590 h60
  text "3" at 9790.34,7470 h60
  text "Top Layer" at 10200.26,7470 h60
  text "Copper" at 11130,7470 h60
  text "2.80mil" at 11989.77,7470 h60
  text "4" at 9790.34,7350 h60
  text "Dielectric1" at 10200.26,7350 h60
  text "FR-4" at 11130,7350 h60
  text "56.00mil" at 11989.77,7350 h60
  text "4.8" at 12639.6,7350 h60
  text "5" at 9790.34,7230 h60
  text "Bottom Layer" at 10200.26,7230 h60
  text "Copper" at 11130,7230 h60
  text "2.80mil" at 11989.77,7230 h60
  text "6" at 9790.34,7110 h60
  text "Bottom Solder" at 10200.26,7110 h60
  text "Solder Resist" at 11130,7110 h60
  text "0.40mil" at 11989.77,7110 h60
  text "3.5" at 12639.6,7110 h60
  text "7" at 9790.34,6990 h60
  text "Bottom Overlay" at 10200.26,6990 h60
  text ".Layer_Name" at 577,-858.49 h60
M13 Component Bodies Top:
  text ".Layer_Name" at 577,-858.49 h60
M14 Component Bodies Bottom:
  text ".Layer_Name" at 577,-858.49 h60
M15 Courtyards Top:
  text ".Layer_Name" at 577,-858.49 h60
M16 Courtyards Bottom:
  text ".Layer_Name" at 577,-858.49 h60
Drill Drawing:
  lines w10: 5656.09,2865.7 5656.09,2879.51 5669.9,2893.32 5656.09,2907.14 5656.09,2920.95 5669.9,2920.95 5683.72,2907.14 5697.53,2920.95 5711.34,2920.95 5711.34,2907.14 5697.53,2893.32 5711.34,2879.51 5711.34,2865.7 5697.53,2865.7 5683.72,2879.51 5669.9,2865.7 5656.09,2865.7 ; 5656.09,3045.27 5711.34,3045.27 5683.72,2990.02 5656.09,3045.27 ; 5656.09,3141.96 5683.72,3114.34 5711.34,3141.96 5683.72,3169.59 5656.09,3141.96 ; 5656.09,3293.91 5711.34,3293.91 5683.72,3238.66 5656.09,3293.91 ; 5667.14,3282.86 5700.29,3282.86 5683.72,3249.71 5667.14,3282.86
  lines w12: 5606,2828.4 7584.02,2828.4 ; 5606,3325.68 7584.02,3325.68 ; 5943.86,2704.08 5943.86,3450 ; 6275.86,2704.08 6275.86,3450 ; 6912.43,2704.08 6912.43,3450 ; 7171.57,2704.08 7171.57,3450 ; 5606,2704.08 7584.02,2704.08 7584.02,3450 5606,3450 5606,2704.08
  text "Symbol" at 5680.59,3362.98 h72
  text "Quantity" at 5981.16,3362.98 h72
  text "Finished Hole Size" at 6313.16,3362.98 h72
  text "Plated" at 6949.72,3362.98 h72
  text "Hole Type" at 7208.86,3362.98 h72
  text "4" at 5981.16,3238.66 h60
  text "8.00mil (0.203mm)" at 6313.16,3238.66 h60
  text "PTH" at 6949.72,3238.66 h60
  text "Round" at 7208.86,3238.66 h60
  text "16" at 5981.16,3114.34 h60
  text "10.00mil (0.254mm)" at 6313.16,3114.34 h60
  text "PTH" at 6949.72,3114.34 h60
  text "Round" at 7208.86,3114.34 h60
  text "1" at 5981.16,2990.02 h60
  text "52.00mil (1.321mm)" at 6313.16,2990.02 h60
  text "PTH" at 6949.72,2990.02 h60
  text "Round" at 7208.86,2990.02 h60
  text "6" at 5981.16,2865.7 h60
  text "80.71mil (2.050mm)" at 6313.16,2865.7 h60
  text "PTH" at 6949.72,2865.7 h60
  text "Round" at 7208.86,2865.7 h60
  text "27 Total" at 5981.16,2741.38 h60
  text ".Layer_Name" at 577,-858.49 h60

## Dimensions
1670,1150 to 1670,284 on Top Overlay
1670,284 to 410,284 on Top Overlay
0,0 to 2000,0 on M2 Board Dimensions
0,0 to 0,1700 on M2 Board Dimensions
0,-400 to 1000,-400 on M2 Board Dimensions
